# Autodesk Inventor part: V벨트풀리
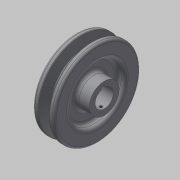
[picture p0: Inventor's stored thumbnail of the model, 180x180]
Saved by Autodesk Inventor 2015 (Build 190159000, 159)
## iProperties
Created: 2015-11
Part Number: V벨트풀리
Material: 강철, 탄소
Document SubType Name: Modeling
Designer: mduedu
Density: 1 g/cm^3
Appearance: 기본값
Author: mduedu
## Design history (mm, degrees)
sketch "스케치1"
  geometry: L1 (-9.5, 0)-(9.5, 0); L2 (0, 0)-(0, 37.7); L3 (-4.825, 37.7)-(-9.5, 37.7); L4 (-9.5, 37.7)-(-9.5, 0); L5 (0, 28.7)-(-2.074, 28.7); L6 (-2.074, 28.7)-(-4.825, 37.7); L7 (4.825, 37.7)-(9.5, 37.7); L8 (9.5, 37.7)-(9.5, 0); L9 (0, 28.7)-(2.074, 28.7); L10 (2.074, 28.7)-(4.825, 37.7); L11 (-9.5, 35)-(9.5, 35); 3 further points
  constraints: 22 end point, 7 point on line, 4 perpendicular, 3 symmetric about line, 1 coincident, 1 horizontal, 1 horizontal alignment, 1 midpoint, 1 vertical
  dimensions: "d0" = 19 distance of L1.start L1.end; "d2" = 75.4 diameter of L2.end L1 (derived); "d3" = 34 deg angle of L10 L6; "d4" = 6.3 distance between parallel lines of L11 L9; "d5" = 2.7 distance between parallel lines of L7 L11; "d6" = 8 distance of point (4, 35) point (-4, 35); "d7" = 70 diameter of L11 L1
revolve "회전1" sketch "스케치1" stored, may be unused: angle "d8" = 90 deg
sketch "스케치2"
  geometry: C1 r 24 at (0, 0); C2 r 13 at (0, 0); 1 further point
  constraints: 2 centre point, 2 coincident
  dimensions: "d9" = 48 diameter of C1; "d10" = 26 diameter of C2
extrude "돌출1" cut sketch "스케치2" distance "d11" = 6; taper "d12" = 0 deg
extrude "돌출3" join sketch "스케치2" distance "d37" = 6; taper "d38" = 0 deg
fillet "모깎기1" dims "d13" = 3
fillet "모깎기2" dims "d14" = 3
fillet "모깎기3" dims "d15" = 1, "d16" = 0.5, "d17" = 2
hole "구멍1" diameter "d20" = 16; stored, may be unused: countersink angle "d24" = 90 deg, drill point angle "d26" = 118 deg; dims "d21" = 6, "d22" = 4, "d23" = 2, "d25" = 8, "d53" = 10, "d54" = 10
sketch "스케치3"
  geometry: L1 (-2.5, 0)-(2.5, 0); L2 (2.5, 0)-(2.5, 10.3); L3 (2.5, 10.3)-(-2.5, 10.3); L4 (-2.5, 10.3)-(-2.5, 0); 2 further points
  constraints: 8 end point, 2 parallel, 1 coincident, 1 horizontal, 1 midpoint, 1 perpendicular
  dimensions: "d27" = 5 distance of L2.end L3.end; "d29" = 10.3 distance of L3.end L1.start
extrude "돌출2" cut sketch "스케치3" stored distance "d30" = 6; taper "d31" = 0 deg
chamfer "모따기1" distance "d32" = 1; stored, may be unused: second distance "d33" = 2, angle "d34" = 45 deg
node "작업 평면1"
sketch "스케치4"
  geometry: L1 (19, -27)-(19, 27) reference; 2 further points
  constraints: 1 horizontal alignment
  dimensions: "d52" = 22 distance from line of L1 point (-3, 0)
hole "구멍2" sketch "스케치4" at (-3, 0) diameter "d42" = 2.459; stored, may be unused: countersink angle "d46" = 90 deg, drill point angle "d48" = 118 deg; dims "d43" = 6, "d44" = 4, "d45" = 2, "d47" = 8
node "솔리드1"
mirror "대칭1"
